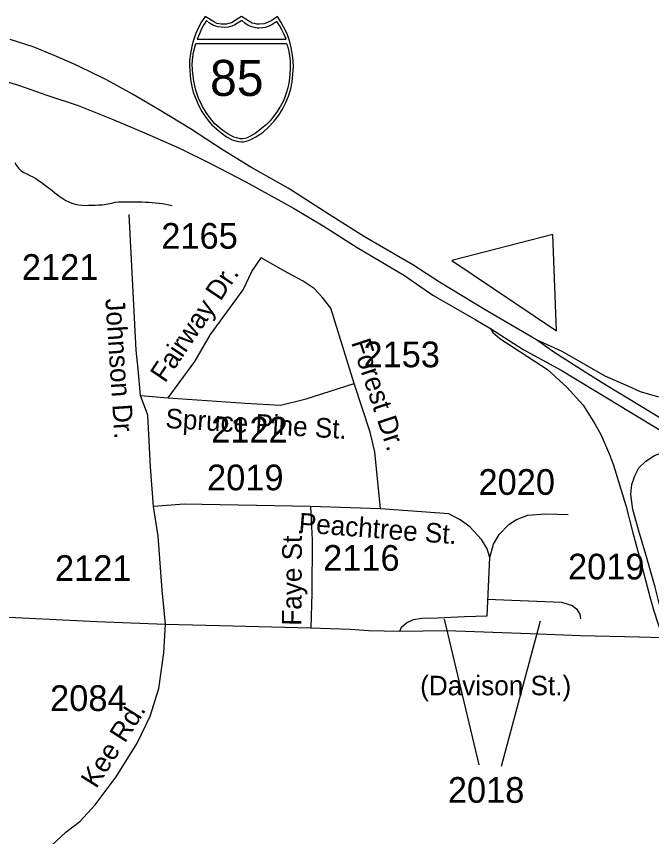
# Model space of a CAD drawing. Extents: x 1364363 to 1407445, y 538563 to 573342.
# Drawn here: x 1385868 to 1388956, y 553422 to 557409 of the extents above; entities that cross this region are included whole.
import ezdxf

# ---------------------------------------------------------------- set-up
doc = ezdxf.new("R2010")
doc.units = 0
for name, color, linetype in [('Default', 7, 'Continuous'), ('Exist Hydrographic Creek Single Shore', 7, 'Continuous'), ('Exist Road Primary Interstate Divided Center Attributed', 7, 'Continuous'), ('Exist Road Primary Interstate Ramp 1 Lane Attributed', 7, 'Continuous'), ('Exist Road Primary Interstate Shield CELL', 7, 'Continuous'), ('Exist Road Primary Interstate Shield Number Label', 7, 'Continuous'), ('Exist Road Primary NC Attributed', 7, 'Continuous'), ('Exist Road Secondary Type 51 Attributed', 7, 'Continuous'), ('Exist Road Secondary Type 51 Label', 7, 'Continuous'), ('Exist Road Secondary Type 51 Number Label', 7, 'Continuous')]:
    doc.layers.add(name, color=color, linetype=linetype)

msp = doc.modelspace()

# ---------------------------------------------------------------- linework, layer by layer
at = {"layer": 'Default'}
msp.add_lwpolyline([(1387985, 556223.4), (1388492.9, 555881.1), (1388476.4, 556348.6), (1387985, 556223.4)], dxfattribs=at)
at = {"layer": 'Exist Hydrographic Creek Single Shore'}
msp.add_lwpolyline([(1385861, 556699), (1385868.4, 556684.2), (1385877.9, 556670.8), (1385890.1, 556660), (1385904, 556651), (1385918.4, 556643.4), (1385933.2, 556636.1), (1385947.9, 556628.8), (1385962.2, 556620.9), (1385976, 556612.1), (1385989.5, 556602.6), (1386002.6, 556592.8), (1386015.6, 556582.7), (1386028.6, 556572.6), (1386041.6, 556562.4), (1386054.5, 556552.3), (1386067.5, 556542.3), (1386080.7, 556532.6), (1386094.1, 556523.2), (1386107.9, 556514.4), (1386122.7, 556507.2), (1386138.1, 556501.2), (1386153.7, 556496.2), (1386169.8, 556492.6), (1386186.2, 556491.1), (1386202.5, 556490.7), (1386218.9, 556490.8), (1386235.4, 556491.1), (1386251.8, 556491.7), (1386268.2, 556492.6), (1386284.6, 556493.8), (1386332.6, 556501.4), (1386348.6, 556505.7), (1386364.7, 556508.4), (1386381.1, 556508.5), (1386397.5, 556508.5), (1386413.9, 556508.5), (1386430.3, 556508.3), (1386446.7, 556508), (1386463.1, 556507.6), (1386479.7, 556507.1), (1386496.1, 556506.4), (1386512.5, 556505.7), (1386528.9, 556504.7), (1386545.2, 556503.7), (1386561.5, 556502.1), (1386577.8, 556499.7), (1386593.9, 556496.7), (1386610, 556493.3), (1386626, 556489.7)], dxfattribs=at)
at = {"layer": 'Exist Road Primary Interstate Divided Center Attributed'}
for points in [[(1388396.7, 555836.3), (1388147.2, 555983.4), (1387924, 556117.7), (1387795.5, 556201.3), (1387560, 556337.2), (1387389.2, 556446.2), (1387189.2, 556574.6), (1387007.6, 556676.1), (1386873.7, 556759.7), (1386715.2, 556862.8), (1386562.8, 556955.3), (1386432, 557031.5), (1386308.9, 557098.7), (1386224.2, 557142), (1386145.7, 557177.8), (1386051.9, 557219.6), (1385949.5, 557261.4), (1385838.7, 557297.2)], [(1385689.4, 557131.5), (1385878, 557074.8), (1386016.5, 557027), (1386168.8, 556976.2), (1386330.4, 556912), (1386502, 556838.9), (1386660.5, 556768.7), (1386811.3, 556694), (1386983.7, 556604.5), (1387215.3, 556477.5), (1387360, 556391), (1387524.6, 556286.4), (1387754, 556149.1), (1387891.7, 556053.5), (1388102, 555934.8), (1388172, 555892.3)], [(1388172, 555892.3), (1388332.2, 555789.7), (1388515.7, 555689), (1388684.7, 555586.9), (1389066.4, 555356.2), (1389278.1, 555224.8), (1389343.7, 555181.4)], [(1389687.5, 555044.2), (1389482.6, 555154), (1389383.4, 555214.9), (1389168.3, 555351.8), (1388949.7, 555486.2), (1388735.8, 555614.6), (1388632.7, 555680.4), (1388485.7, 555774.3), (1388396.7, 555836.3)]]:
    msp.add_lwpolyline(points, dxfattribs=at)
at = {"layer": 'Exist Road Primary Interstate Ramp 1 Lane Attributed'}
for points in [[(1388172, 555892.3), (1388183.3, 555873.1), (1388217.5, 555843.3), (1388450.3, 555692.8), (1388543.1, 555607.5), (1388623.8, 555519.1), (1388679.8, 555428), (1388711.2, 555373.5), (1388750.7, 555280.2), (1388771.1, 555227.1), (1388830.9, 555032.5), (1388864.4, 554898.5), (1388900.9, 554768.2), (1388950.6, 554576.1), (1388965.5, 554524.2), (1389009, 554389.8)], [(1389601.7, 555518.5), (1389494.2, 555519.4), (1389356.8, 555520.3), (1389169.4, 555528.2), (1389129.8, 555532), (1389065.9, 555541.7), (1388979.7, 555562.3), (1388902.1, 555584.6), (1388844.6, 555609.6), (1388729.8, 555660.6), (1388520.3, 555780.2), (1388396.7, 555836.3)], [(1389042, 554388.5), (1389003.8, 554515.1), (1388991.5, 554563.8), (1388972.6, 554635.2), (1388927.8, 554794.1), (1388892.3, 554913.8), (1388865.1, 555012.5), (1388854.8, 555085.7), (1388858.9, 555133.1), (1388873.9, 555175.3), (1388893, 555214.1), (1388927.7, 555247.5), (1388969.2, 555275.5), (1389006.7, 555289.1), (1389057.1, 555292.5), (1389119, 555282.9), (1389175.6, 555263.2), (1389343.7, 555181.4)]]:
    msp.add_lwpolyline(points, dxfattribs=at)
at = {"layer": 'Exist Road Primary Interstate Shield CELL'}
for points in [[(1386962.3, 556798.9), (1386971.7, 556799.8), (1386984.5, 556802.3), (1386996.9, 556806.3), (1387011, 556812.6), (1387031.8, 556824.1), (1387048.6, 556833.9), (1387067.9, 556846.9), (1387094, 556870.6), (1387120.1, 556898.1), (1387143.1, 556929.1), (1387161.3, 556958.1), (1387177.4, 556991.3), (1387190.8, 557022.2), (1387201.5, 557057.5), (1387208.5, 557091.7), (1387212.1, 557127.4), (1387214.5, 557167), (1387211.8, 557211.5), (1387204.1, 557257.1), (1387196.8, 557285.5), (1387185.8, 557319.4), (1387176.8, 557341.1), (1387155.9, 557379.5), (1387137.2, 557409.1), (1387110, 557389.9), (1387092.2, 557380.5), (1387081.3, 557375.6), (1387070.2, 557373.5), (1387049.7, 557371), (1387036.8, 557371.5), (1387024.9, 557374.2), (1387014.7, 557376.4), (1387006.5, 557380.5), (1386962.3, 557409.1), (1386918, 557380.5), (1386908.7, 557376.2), (1386899.2, 557374.2), (1386890, 557371.7), (1386874.9, 557371), (1386863.3, 557371.3), (1386851.5, 557373.5), (1386842.1, 557375.4), (1386831.6, 557380.5), (1386786.5, 557409.1), (1386768.7, 557383.4), (1386754.3, 557358), (1386738.9, 557322.1), (1386729.4, 557294.2), (1386722.6, 557271.4), (1386714.2, 557229.4), (1386709.9, 557192.8), (1386709.1, 557167), (1386713.9, 557102.5), (1386720.9, 557068.1), (1386728.2, 557040.3), (1386752, 556980.3), (1386770, 556946.7), (1386785.4, 556922.5), (1386806.9, 556895.4), (1386818.6, 556882.4), (1386863.4, 556843.2), (1386893.4, 556822.8), (1386917.3, 556809.9), (1386928.5, 556805.6), (1386946.1, 556800.7)], [(1386791.8, 557388.4), (1386780.8, 557371.4), (1386768.2, 557348.6), (1386758, 557324.9), (1386747.7, 557298.8), (1387179.2, 557298.6), (1387169.2, 557321), (1387158.4, 557343.6), (1387147.2, 557364.1), (1387133.4, 557384), (1387109.2, 557368.8), (1387091.6, 557360.5), (1387077.4, 557355.6), (1387065.5, 557352.9), (1387046.9, 557351.4), (1387038.5, 557351.9), (1387012.6, 557357.8), (1386995.1, 557364.9), (1386978.4, 557376.1), (1386964.8, 557388.8), (1386930.6, 557368.1), (1386915.5, 557361.4), (1386898, 557357), (1386878.9, 557354.6), (1386849.5, 557357.8), (1386826.4, 557365.7), (1386806.6, 557376.1)], [(1387181.8, 557277.3), (1387186.4, 557265.1), (1387192.8, 557238.1), (1387196.1, 557217.2), (1387199.5, 557193.3), (1387198.3, 557152.1), (1387196.3, 557109.5), (1387192.4, 557084.3), (1387187.2, 557061.4), (1387180, 557035.9), (1387168.5, 557002.1), (1387152.6, 556973.5), (1387132.7, 556941.6), (1387111.2, 556913.8), (1387101.9, 556902.2), (1387084.2, 556883.5), (1387052, 556857.7), (1387028.5, 556840.1), (1387000.3, 556823.4), (1386986, 556817.1), (1386969.3, 556813.6), (1386955.6, 556814.6), (1386939, 556819), (1386925.5, 556822.6), (1386896.1, 556838.6), (1386872.2, 556854.5), (1386832.5, 556887.1), (1386811, 556912.2), (1386791, 556941.6), (1386773.1, 556971.7), (1386754, 557011.4), (1386740.6, 557051.3), (1386730.8, 557094.4), (1386724.2, 557147), (1386723.4, 557179.1), (1386725.4, 557209.9), (1386728.3, 557226.1), (1386732.3, 557246.1), (1386740.1, 557277.1)]]:
    msp.add_lwpolyline(points, close=True, dxfattribs=at)
at = {"layer": 'Exist Road Primary NC Attributed'}
for points in [[(1385203.6, 554513), (1385280.8, 554517.4), (1385498.7, 554505), (1386258.9, 554467.9), (1386592.8, 554454.5)], [(1386592.8, 554454.5), (1386919.8, 554447), (1387299.2, 554436.6)], [(1387299.2, 554436.6), (1387490, 554430.6), (1387579.3, 554424.6), (1387732.8, 554421.6)], [(1387732.8, 554421.6), (1387958.1, 554423.9), (1388366, 554409.4), (1388610.8, 554399.2)], [(1388610.8, 554399.2), (1388896.8, 554393.1), (1389009, 554389.8)]]:
    msp.add_lwpolyline(points, dxfattribs=at)
at = {"layer": 'Exist Road Secondary Type 51 Attributed'}
for p, q in [((1386471.2, 555566.8), (1386605.8, 555554.5)), ((1387638.5, 555015.9), (1387297.6, 555026.3)), ((1388156.8, 554494.8), (1388169.1, 554778.5))]:
    msp.add_line(p, q, dxfattribs=at)
for points in [[(1386471.2, 555566.8), (1386459.7, 555693.6), (1386450.5, 555787.4), (1386417.1, 556446.9)], [(1386605.8, 555554.5), (1386735.1, 555731.1), (1386811.5, 555862.4), (1386970.7, 556079.9), (1387012.9, 556168.5), (1387057.6, 556235.7)], [(1387509.3, 555625), (1387396.3, 555990.3), (1387354.6, 556044.6), (1387316.1, 556086.4), (1387262.3, 556122.2), (1387189.9, 556161), (1387057.6, 556235.7)], [(1386605.8, 555554.5), (1386982.2, 555529.5), (1387152.2, 555519), (1387276.9, 555550.4), (1387509.3, 555625)], [(1387638.5, 555015.9), (1387610.1, 555292.1), (1387588.5, 555387.6), (1387509.3, 555625)], [(1386535.1, 555026.3), (1386519.7, 555218.9), (1386507.1, 555471.6), (1386471.2, 555566.8)], [(1387297.6, 555026.3), (1386684.4, 555038.3), (1386535.1, 555026.3)], [(1386592.8, 554454.5), (1386577.6, 554620.5), (1386557, 554883.1), (1386535.1, 555026.3)], [(1387297.6, 555026.3), (1387305.1, 554865.6), (1387303.6, 554605.5), (1387299.2, 554436.6)], [(1388169.1, 554778.5), (1388156.8, 554821.8), (1388129.1, 554866.6), (1388072.1, 554927.8), (1388026, 554962.1), (1387970.6, 554990.5), (1387638.5, 555015.9)], [(1388169.1, 554778.5), (1388187.6, 554844.2), (1388214, 554890.7), (1388261, 554939.8), (1388298.7, 554964.3), (1388354.1, 554985.2), (1388440.3, 554991.2), (1388549.6, 554988.2)], [(1388156.8, 554576), (1388517.7, 554561.4), (1388569.2, 554546.1), (1388591.1, 554529.9), (1388606.2, 554502.8), (1388610.8, 554480.4)], [(1387732.8, 554421.6), (1387740.5, 554441), (1387763.6, 554461.9), (1387799, 554476.9), (1387839, 554484.3), (1387915.9, 554485.8), (1388046.7, 554491.8), (1388156.8, 554494.8)], [(1386314.8, 552661.1), (1386213.9, 552905.2), (1386092.3, 553218), (1386044.4, 553325), (1386039.5, 553379.2), (1386108.8, 553443.8), (1386175.9, 553496.3), (1386251.8, 553576.8), (1386352.6, 553712.8), (1386456.1, 553876.8), (1386518.8, 554007.4), (1386560.7, 554142.1), (1386585.2, 554316.2), (1386592.8, 554454.5)]]:
    msp.add_lwpolyline(points, dxfattribs=at)
at = {"layer": 'Exist Road Secondary Type 51 Number Label'}
for p, q in [((1387947, 554479.8), (1388115.6, 553770.5)), ((1388414.1, 554469.3), (1388224.4, 553763.5))]:
    msp.add_line(p, q, dxfattribs=at)

# ---------------------------------------------------------------- texts
at = {"layer": 'Exist Road Primary Interstate Shield Number Label'}
msp.add_text('85', height=175, dxfattribs=at).set_placement((1386809.4, 557022.7))
at = {"layer": 'Exist Road Secondary Type 51 Label'}
for s, rotation, p in [('Fairway Dr.', 55.9513, (1386590.8, 555623.7)), ('Johnson Dr.', 273.8083, (1386300.3, 556036.1)), ('Forest Dr.', 288.4624, (1387494.6, 555824.4)), ('Spruce Pine St.', 356.4829, (1386590.5, 555409.1)), ('Peachtree St.', 355.6288, (1387238.1, 554901.8)), ('Faye St.', 89.6835, (1387253.5, 554447.4)), ('Kee Rd.', 57.7301, (1386256, 553652.1))]:
    msp.add_text(s, height=95, rotation=rotation, dxfattribs=at).set_placement(p)
msp.add_text('(Davison St.)', height=95, dxfattribs=at).set_placement((1387830.8, 554109.2))
at = {"layer": 'Exist Road Secondary Type 51 Number Label'}
for s, p in [('2165', (1386572.6, 556279.9)), ('2121', (1385895, 556128.4)), ('2153', (1387555.1, 555703.6)), ('2122', (1386815.2, 555337.7)), ('2019', (1386795.1, 555105.6)), ('2020', (1388114.3, 555083.5)), ('2116', (1387359.1, 554714.4)), ('2121', (1386055.9, 554665)), ('2019', (1388549.4, 554672.2)), ('2084', (1386032.1, 554032.9)), ('2018', (1387965.4, 553586.5))]:
    msp.add_text(s, height=125, dxfattribs=at).set_placement(p)

doc.saveas('drawing.dxf')
